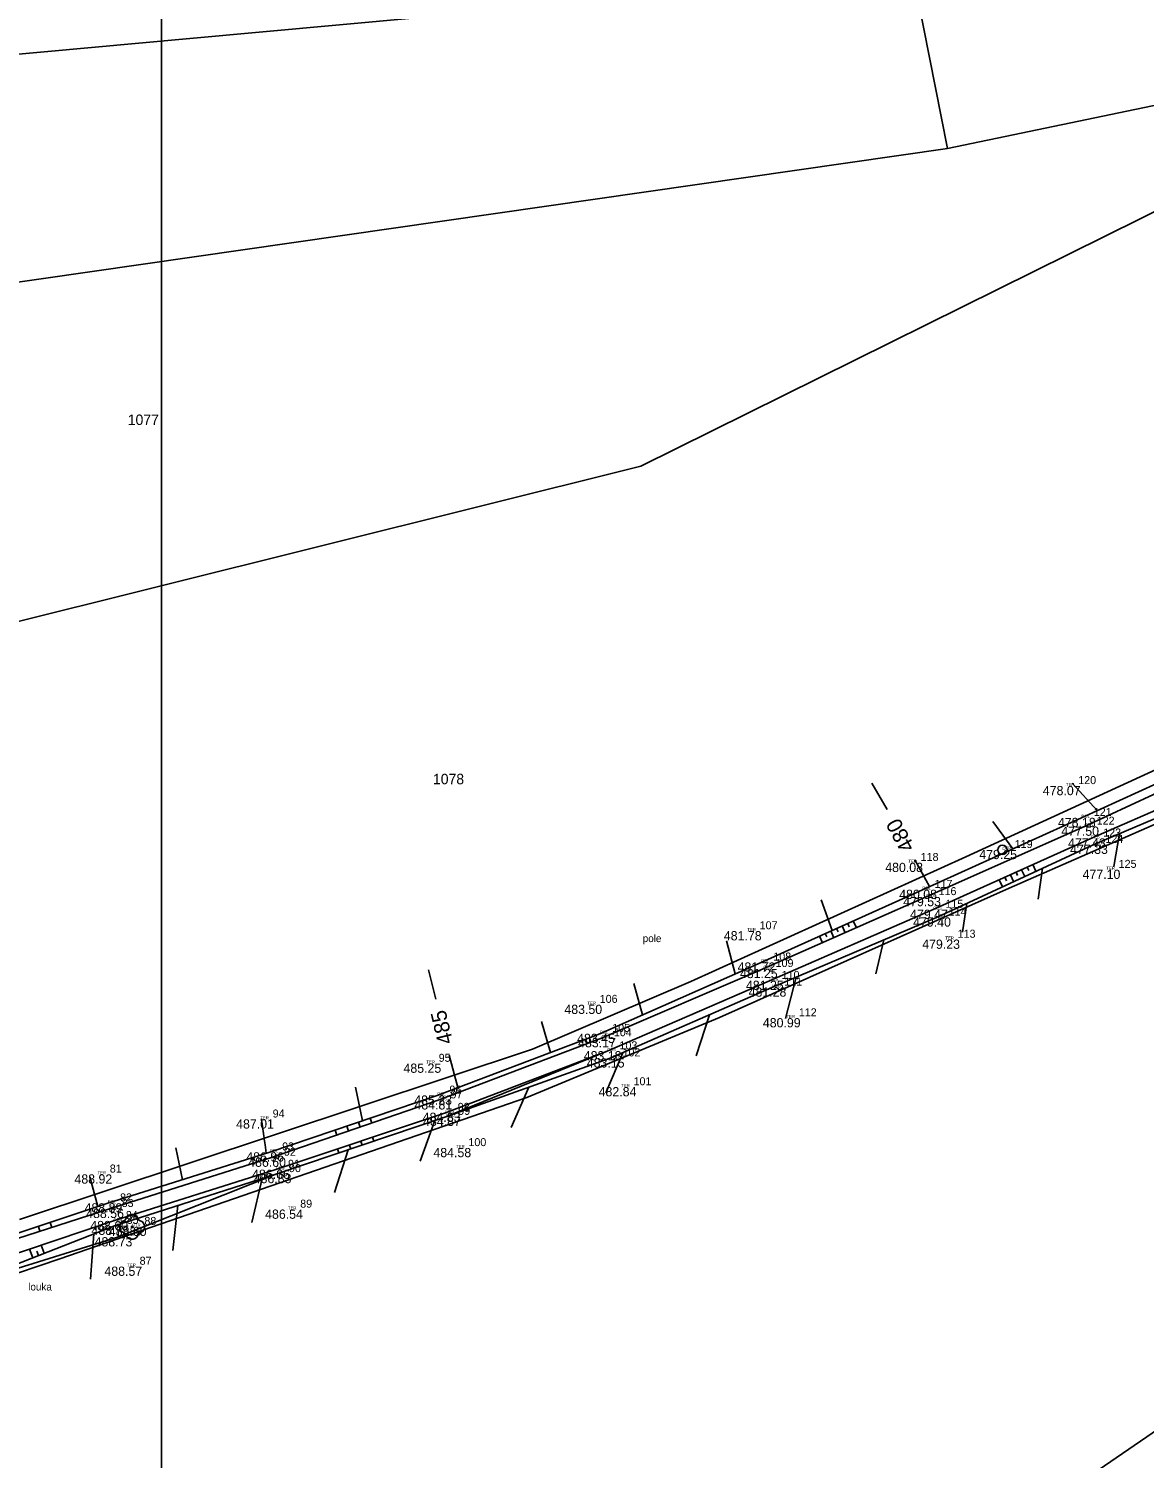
# Model space of a CAD drawing. Extents: x -604848 to -603227, y -1111879 to -1109838.
# Drawn here: x -603773.6 to -603592.3, y -1110449.9 to -1110217.6 of the extents above; entities that cross this region are included whole.
import ezdxf

# ---------------------------------------------------------------- set-up
doc = ezdxf.new("R2010")
doc.units = 0
for name, color, linetype in [('1', 7, 'Continuous'), ('10', 7, 'Continuous'), ('14', 7, 'Continuous'), ('18', 7, 'Continuous'), ('19', 7, 'Continuous'), ('20', 7, 'Continuous'), ('3', 7, 'Continuous'), ('4', 7, 'Continuous'), ('6', 7, 'Continuous'), ('7', 7, 'Continuous'), ('8', 7, 'Continuous'), ('9', 7, 'Continuous'), ('Default', 7, 'Continuous')]:
    doc.layers.add(name, color=color, linetype=linetype)

# ---------------------------------------------------------------- blocks, each defined once
blk = doc.blocks.new('POINT_DISPLAY')
at = {"layer": 'Default'}
blk.add_line((0, 0), (0, 0), dxfattribs=at)
blk = doc.blocks.new('Z313')
at = {"layer": '3'}
for p, q in [((-2, 0.2), (-1.9, 0.5)), ((-2, -0.2), (-2, 0.2)), ((-1.9, 0.5), (-1.7, 0.8)), ((-1.7, 0.8), (-1.1, 1.1)), ((-1.1, 1.1), (-0.9, 1.5)), ((-0.9, 1.5), (-0.7, 1.8)), ((-0.7, 1.8), (-0.2, 2)), ((-0.2, 2), (0.2, 2)), ((-0.1, -0.1), (-0.1, 0.1)), ((-0.1, 0.1), (0.1, 0.1)), ((0.1, 0.1), (0.1, -0.1)), ((0.2, 2), (0.7, 1.8)), ((0.7, 1.8), (0.9, 1.5)), ((0.9, 1.5), (1.1, 1.1)), ((1.1, 1.1), (1.7, 0.8)), ((1.7, 0.8), (1.9, 0.5)), ((1.9, 0.5), (2, 0.2)), ((2, 0.2), (2, -0.2)), ((-1.8, -0.7), (-2, -0.2)), ((-1.5, -0.9), (-1.8, -0.7)), ((-1.1, -1.1), (-1.5, -0.9)), ((-0.8, -1.7), (-1.1, -1.1)), ((-0.5, -1.9), (-0.8, -1.7)), ((-0.2, -2), (-0.5, -1.9)), ((0.2, -2), (-0.2, -2)), ((0.1, -0.1), (-0.1, -0.1)), ((0.5, -1.9), (0.2, -2)), ((0.8, -1.7), (0.5, -1.9)), ((1.1, -1.1), (0.8, -1.7)), ((1.5, -0.9), (1.1, -1.1)), ((1.8, -0.7), (1.5, -0.9)), ((2, -0.2), (1.8, -0.7))]:
    blk.add_line(p, q, dxfattribs=at)

msp = doc.modelspace()

# ---------------------------------------------------------------- linework, layer by layer
at = {"layer": '1'}
for p, q in [((-603748.02, -1110219.29), (-603630.01, -1110208.48)), ((-603624.32, -1110237.13), (-603630.01, -1110208.48)), ((-603943.43, -1110237.19), (-603748.02, -1110219.29)), ((-603550.28, -1110221.64), (-603624.32, -1110237.13)), ((-603548.21, -1110226.34), (-603674.17, -1110288.7)), ((-603771.57, -1110258.26), (-603624.32, -1110237.13)), ((-603918.81, -1110279.39), (-603771.57, -1110258.26)), ((-603674.17, -1110288.7), (-603780.53, -1110315.22)), ((-603621.37, -1110352.15), (-603565.71, -1110326.59)), ((-603572.67, -1110338.96), (-603614.3, -1110357.26)), ((-603666.05, -1110372.43), (-603621.37, -1110352.15)), ((-603614.3, -1110357.26), (-603661.36, -1110378.28)), ((-603691.73, -1110383.39), (-603666.05, -1110372.43)), ((-603661.36, -1110378.28), (-603692.66, -1110391.24)), ((-603775.1, -1110411.08), (-603691.73, -1110383.39)), ((-603692.66, -1110391.24), (-603768.54, -1110417.48)), ((-603540.65, -1110411.31), (-603658.23, -1110491.66)), ((-603768.54, -1110417.48), (-603859.09, -1110447.69))]:
    msp.add_line(p, q, dxfattribs=at)
msp.add_lwpolyline([(-603752.05, -1110677.81), (-603752.05, -1109837.81), (-604346.05, -1109837.81), (-604346.05, -1110677.81), (-603752.05, -1110677.81)], dxfattribs=at)
at = {"layer": '10'}
for p, q in [((-603602.56, -1110345.83), (-603575.88, -1110333.62)), ((-603573.72, -1110338.82), (-603600.67, -1110350.19)), ((-603628.41, -1110357.5), (-603602.56, -1110345.83)), ((-603600.67, -1110350.19), (-603626.13, -1110362)), ((-603654.62, -1110369.31), (-603628.41, -1110357.5)), ((-603626.13, -1110362), (-603652.84, -1110373.37)), ((-603680.8, -1110380.9), (-603654.62, -1110369.31)), ((-603652.84, -1110373.37), (-603679.12, -1110384.88)), ((-603707.24, -1110390.92), (-603680.8, -1110380.9)), ((-603679.12, -1110384.88), (-603705.81, -1110394.37)), ((-603734.42, -1110400.15), (-603707.24, -1110390.92)), ((-603705.81, -1110394.37), (-603733.31, -1110403.67)), ((-603760.76, -1110408.43), (-603734.42, -1110400.15)), ((-603759.18, -1110413.94), (-603733.31, -1110403.67)), ((-603787.01, -1110417.17), (-603760.76, -1110408.43)), ((-603785.27, -1110422.1), (-603759.18, -1110413.94))]:
    msp.add_line(p, q, dxfattribs=at)
at = {"layer": '4'}
for p, q in [((-603602.08, -1110347.24), (-603575.32, -1110334.85)), ((-603574.24, -1110337.54), (-603601.02, -1110349.16)), ((-603627.77, -1110358.68), (-603602.08, -1110347.24)), ((-603601.02, -1110349.16), (-603626.65, -1110360.74)), ((-603654.25, -1110370.36), (-603627.77, -1110358.68)), ((-603626.65, -1110360.74), (-603653.27, -1110372.29)), ((-603680.53, -1110381.6), (-603654.25, -1110370.36)), ((-603653.27, -1110372.29), (-603679.62, -1110383.72)), ((-603707.06, -1110391.7), (-603680.53, -1110381.6)), ((-603679.62, -1110383.72), (-603705.9, -1110393.72)), ((-603734.13, -1110401.01), (-603707.06, -1110391.7)), ((-603705.9, -1110393.72), (-603733.47, -1110402.97)), ((-603760.5, -1110409.33), (-603734.13, -1110401.01)), ((-603733.47, -1110402.97), (-603759.82, -1110411.3)), ((-603786.7, -1110417.78), (-603760.5, -1110409.33)), ((-603759.82, -1110411.3), (-603785.93, -1110420.05))]:
    msp.add_line(p, q, dxfattribs=at)
at = {"layer": '6'}
msp.add_circle((-603615.4, -1110351.03), 0.75, dxfattribs=at)
at = {"layer": '7'}
for p, q in [((-603634.14, -1110344.49), (-603636.59, -1110340.21)), ((-603604.07, -1110340.22), (-603600.01, -1110344.66)), ((-603616.93, -1110346.43), (-603613.69, -1110350.85)), ((-603596.38, -1110348.38), (-603597.28, -1110353.72)), ((-603629.65, -1110352.63), (-603627.25, -1110356.98)), ((-603608.89, -1110354), (-603609.58, -1110359.05)), ((-603644.87, -1110359.15), (-603643.06, -1110364.11)), ((-603621.17, -1110359.7), (-603621.86, -1110364.38)), ((-603660.23, -1110365.79), (-603658.82, -1110371.17)), ((-603634.66, -1110365.63), (-603635.98, -1110371.19)), ((-603707.43, -1110375.29), (-603708.67, -1110370.51)), ((-603648.9, -1110371.69), (-603650.63, -1110378.42)), ((-603675.28, -1110372.71), (-603673.9, -1110377.85)), ((-603690.29, -1110378.91), (-603688.81, -1110383.93)), ((-603663.01, -1110377.83), (-603665.18, -1110384.49)), ((-603705.81, -1110394.37), (-603679.62, -1110383.72)), ((-603677.07, -1110383.98), (-603679.86, -1110390.49)), ((-603705.27, -1110384.38), (-603703.86, -1110389.64)), ((-603720.49, -1110389.6), (-603719.36, -1110395.03)), ((-603692.33, -1110389.58), (-603695.21, -1110396.15)), ((-603707.64, -1110394.99), (-603709.98, -1110401.58)), ((-603748.64, -1110404.62), (-603749.69, -1110399.44)), ((-603721.69, -1110399.74), (-603723.91, -1110406.68)), ((-603763.65, -1110404.15), (-603762.39, -1110408.97)), ((-603759.68, -1110412.07), (-603733.31, -1110403.67)), ((-603735.67, -1110404.42), (-603737.35, -1110411.53)), ((-603749.35, -1110408.78), (-603750.21, -1110416.1)), ((-603785.27, -1110422.1), (-603759.68, -1110412.07)), ((-603763.04, -1110413.39), (-603763.59, -1110420.74))]:
    msp.add_line(p, q, dxfattribs=at)
msp.add_open_spline([(-603735.8, -1110394.74), (-603735.74, -1110395.14), (-603735.69, -1110395.54), (-603735.64, -1110395.95), (-603735.42, -1110397.41), (-603735.21, -1110398.87), (-603735, -1110400.33)], degree=3, dxfattribs=at)
at = {"layer": '8'}
for p, q in [((-603611.37, -1110353.83), (-603611.12, -1110354.38)), ((-603610.45, -1110353.42), (-603609.97, -1110354.5)), ((-603615.92, -1110355.89), (-603615.41, -1110357.02)), ((-603615.01, -1110355.48), (-603614.76, -1110356.04)), ((-603614.1, -1110355.07), (-603613.6, -1110356.18)), ((-603613.19, -1110354.66), (-603612.94, -1110355.21)), ((-603612.28, -1110354.25), (-603611.78, -1110355.34)), ((-603640.54, -1110362.97), (-603640.28, -1110363.53)), ((-603639.63, -1110362.56), (-603639.12, -1110363.69)), ((-603645.1, -1110365.02), (-603644.61, -1110366.11)), ((-603644.18, -1110364.61), (-603643.94, -1110365.16)), ((-603643.27, -1110364.2), (-603642.78, -1110365.3)), ((-603642.36, -1110363.79), (-603642.11, -1110364.34)), ((-603641.45, -1110363.38), (-603640.95, -1110364.5)), ((-603720.02, -1110395.25), (-603719.74, -1110396.06)), ((-603718.12, -1110394.61), (-603717.85, -1110395.42)), ((-603723.81, -1110396.54), (-603723.53, -1110397.36)), ((-603721.91, -1110395.9), (-603721.64, -1110396.71)), ((-603717.51, -1110398.33), (-603717.72, -1110397.69)), ((-603723.19, -1110400.25), (-603723.41, -1110399.59)), ((-603721.29, -1110399.61), (-603721.51, -1110398.96)), ((-603719.4, -1110398.97), (-603719.62, -1110398.32)), ((-603770.13, -1110411.55), (-603769.86, -1110412.35)), ((-603772.03, -1110412.18), (-603771.77, -1110412.96)), ((-603772.95, -1110417.27), (-603773.49, -1110415.88)), ((-603772.02, -1110416.91), (-603772.28, -1110416.23)), ((-603771.08, -1110416.54), (-603771.59, -1110415.24))]:
    msp.add_line(p, q, dxfattribs=at)

# ---------------------------------------------------------------- block references
at = {"layer": '18'}
for p in [(-603605.08, -1110340.65), (-603602.56, -1110345.83), (-603602.08, -1110347.24), (-603601.02, -1110349.16), (-603615.4, -1110351.03), (-603600.67, -1110350.19), (-603630.68, -1110353.13), (-603598.51, -1110354.25), (-603628.41, -1110357.5), (-603627.77, -1110358.68), (-603626.65, -1110360.74), (-603626.13, -1110362), (-603656.84, -1110364.23), (-603624.67, -1110365.6), (-603654.62, -1110369.31), (-603654.25, -1110370.36), (-603653.27, -1110372.29), (-603652.84, -1110373.37), (-603682.83, -1110376.18), (-603650.48, -1110378.36), (-603680.8, -1110380.9), (-603680.53, -1110381.6), (-603679.62, -1110383.72), (-603708.99, -1110385.74), (-603679.12, -1110384.88), (-603707.24, -1110390.92), (-603677.33, -1110389.56), (-603707.06, -1110391.7), (-603735.97, -1110394.8), (-603705.9, -1110393.72), (-603705.81, -1110394.37), (-603734.42, -1110400.15), (-603704.16, -1110399.45), (-603734.13, -1110401.01), (-603762.43, -1110403.74), (-603733.47, -1110402.97), (-603733.31, -1110403.67), (-603760.76, -1110408.43), (-603760.5, -1110409.33), (-603731.49, -1110409.45), (-603759.82, -1110411.3), (-603759.68, -1110412.07), (-603759.18, -1110413.94), (-603756.81, -1110412.25), (-603757.58, -1110418.72)]:
    msp.add_blockref('POINT_DISPLAY', p, dxfattribs=at)
at = {"layer": '3'}
msp.add_blockref('Z313', (-603756.81, -1110412.25), dxfattribs=at)

# ---------------------------------------------------------------- texts
at = {"layer": '14'}
for s, p in [('1077', (-603757.51, -1110282.02)), ('1078', (-603707.92, -1110340.37))]:
    msp.add_text(s, height=1.7, dxfattribs=at).set_placement(p)
at = {"layer": '18'}
for s, p in [('TER', (-603605.08, -1110340.65)), ('POL', (-603602.56, -1110345.83)), ('CES', (-603602.08, -1110347.24)), ('CES', (-603601.02, -1110349.16)), ('OTP', (-603615.4, -1110351.03)), ('LOU', (-603600.67, -1110350.19)), ('TER', (-603630.68, -1110353.13)), ('TER', (-603598.51, -1110354.25)), ('POL', (-603628.41, -1110357.5)), ('CES', (-603627.77, -1110358.68)), ('CES', (-603626.65, -1110360.74)), ('LOU', (-603626.13, -1110362)), ('TER', (-603656.84, -1110364.23)), ('TER', (-603624.67, -1110365.6)), ('POL', (-603654.62, -1110369.31)), ('CES', (-603654.25, -1110370.36)), ('CES', (-603653.27, -1110372.29)), ('LOU', (-603652.84, -1110373.37)), ('TER', (-603682.83, -1110376.18)), ('TER', (-603650.48, -1110378.36)), ('POL', (-603680.8, -1110380.9)), ('CES', (-603680.53, -1110381.6)), ('CES', (-603679.62, -1110383.72)), ('TER', (-603708.99, -1110385.74)), ('LOU', (-603679.12, -1110384.88)), ('POL', (-603707.24, -1110390.92)), ('TER', (-603677.33, -1110389.56)), ('CES', (-603707.06, -1110391.7)), ('CES', (-603705.9, -1110393.72)), ('TER', (-603735.97, -1110394.8)), ('LOU', (-603705.81, -1110394.37)), ('POL', (-603734.42, -1110400.15)), ('TER', (-603704.16, -1110399.45)), ('CES', (-603734.13, -1110401.01)), ('CES', (-603733.47, -1110402.97)), ('TER', (-603762.43, -1110403.74)), ('LOU', (-603733.31, -1110403.67)), ('POL', (-603760.76, -1110408.43)), ('CES', (-603760.5, -1110409.33)), ('TER', (-603731.49, -1110409.45)), ('CES', (-603759.82, -1110411.3)), ('TER', (-603759.68, -1110412.07)), ('STR', (-603756.81, -1110412.25)), ('LOU', (-603759.18, -1110413.94)), ('TER', (-603757.58, -1110418.72))]:
    msp.add_text(s, height=0.5, dxfattribs=at).set_placement(p)
at = {"layer": '19'}
for s, p in [('120', (-603603.08, -1110340.35)), ('121', (-603600.56, -1110345.53)), ('122', (-603600.08, -1110346.94)), ('123', (-603599.02, -1110348.86)), ('124', (-603598.67, -1110349.89)), ('118', (-603628.68, -1110352.83)), ('119', (-603613.4, -1110350.73)), ('125', (-603596.51, -1110353.95)), ('117', (-603626.41, -1110357.2)), ('116', (-603625.77, -1110358.38)), ('115', (-603624.65, -1110360.44)), ('114', (-603624.13, -1110361.7)), ('107', (-603654.84, -1110363.93)), ('113', (-603622.67, -1110365.3)), ('108', (-603652.62, -1110369.01)), ('109', (-603652.25, -1110370.06)), ('110', (-603651.27, -1110371.99)), ('111', (-603650.84, -1110373.07)), ('106', (-603680.83, -1110375.88)), ('112', (-603648.48, -1110378.06)), ('105', (-603678.8, -1110380.6)), ('104', (-603678.53, -1110381.3)), ('103', (-603677.62, -1110383.42)), ('102', (-603677.12, -1110384.58)), ('95', (-603706.99, -1110385.45)), ('101', (-603675.33, -1110389.26)), ('96', (-603705.24, -1110390.62)), ('97', (-603705.06, -1110391.4)), ('94', (-603733.97, -1110394.5)), ('98', (-603703.9, -1110393.42)), ('99', (-603703.81, -1110394.07)), ('100', (-603702.16, -1110399.15)), ('93', (-603732.42, -1110399.85)), ('92', (-603732.13, -1110400.71)), ('81', (-603760.43, -1110403.44)), ('91', (-603731.47, -1110402.67)), ('90', (-603731.31, -1110403.37)), ('82', (-603758.76, -1110408.13)), ('83', (-603758.5, -1110409.03)), ('89', (-603729.49, -1110409.15)), ('84', (-603757.82, -1110411)), ('85', (-603757.68, -1110411.77)), ('88', (-603754.81, -1110411.95)), ('86', (-603757.18, -1110413.64)), ('87', (-603755.58, -1110418.42))]:
    msp.add_text(s, height=1.3, dxfattribs=at).set_placement(p)
at = {"layer": '20'}
for s, p in [('478.07 ', (-603608.83, -1110342.15)), ('478.18 ', (-603606.38, -1110347.33)), ('477.50 ', (-603605.84, -1110348.74)), ('477.43 ', (-603604.73, -1110350.66)), ('479.25 ', (-603619.16, -1110352.53)), ('477.33 ', (-603604.4, -1110351.69)), ('480.08 ', (-603634.44, -1110354.63)), ('477.10 ', (-603602.37, -1110355.75)), ('480.08 ', (-603632.17, -1110359)), ('479.53 ', (-603631.52, -1110360.18)), ('479.47 ', (-603630.4, -1110362.24)), ('479.40 ', (-603629.9, -1110363.5)), ('481.78 ', (-603660.66, -1110365.73)), ('479.23 ', (-603628.43, -1110367.1)), ('481.72 ', (-603658.43, -1110370.81)), ('481.25 ', (-603658.05, -1110371.86)), ('481.25 ', (-603657.07, -1110373.79)), ('481.28 ', (-603656.64, -1110374.87)), ('483.50 ', (-603686.57, -1110377.68)), ('480.99 ', (-603654.32, -1110379.86)), ('483.45 ', (-603684.5, -1110382.4)), ('483.17 ', (-603684.34, -1110383.1)), ('483.18 ', (-603683.42, -1110385.22)), ('485.25 ', (-603712.71, -1110387.24)), ('483.15 ', (-603682.93, -1110386.38)), ('485.23 ', (-603710.96, -1110392.42)), ('482.84 ', (-603681, -1110391.06)), ('484.81 ', (-603710.93, -1110393.2)), ('487.01 ', (-603739.9, -1110396.3)), ('484.83 ', (-603709.59, -1110395.22)), ('484.87 ', (-603709.52, -1110395.87)), ('486.96 ', (-603738.26, -1110401.65)), ('484.58 ', (-603707.85, -1110400.95)), ('486.60 ', (-603737.94, -1110402.51)), ('488.92 ', (-603766.17, -1110405.24)), ('486.66 ', (-603737.31, -1110404.47)), ('486.83 ', (-603737.05, -1110405.17)), ('488.89 ', (-603764.53, -1110409.93)), ('488.56 ', (-603764.27, -1110410.83)), ('486.54 ', (-603735.19, -1110410.95)), ('488.60 ', (-603763.6, -1110412.8)), ('488.75 ', (-603763.4, -1110413.57)), ('488.73 ', (-603762.9, -1110415.44)), ('488.60 ', (-603760.59, -1110413.75)), ('488.57 ', (-603761.3, -1110420.22))]:
    msp.add_text(s, height=1.5, dxfattribs=at).set_placement(p)
at = {"layer": '7'}
for s, rotation, p in [('480', 118.8, (-603629.56, -1110350.55)), ('485', 103.5, (-603704.62, -1110382.3))]:
    msp.add_text(s, height=2.5, rotation=rotation, dxfattribs=at).set_placement(p)
at = {"layer": '9'}
for s, p in [('pole', (-603673.84, -1110366.01)), ('louka', (-603773.68, -1110422.6))]:
    msp.add_text(s, height=1.2, dxfattribs=at).set_placement(p)

doc.saveas('drawing.dxf')
